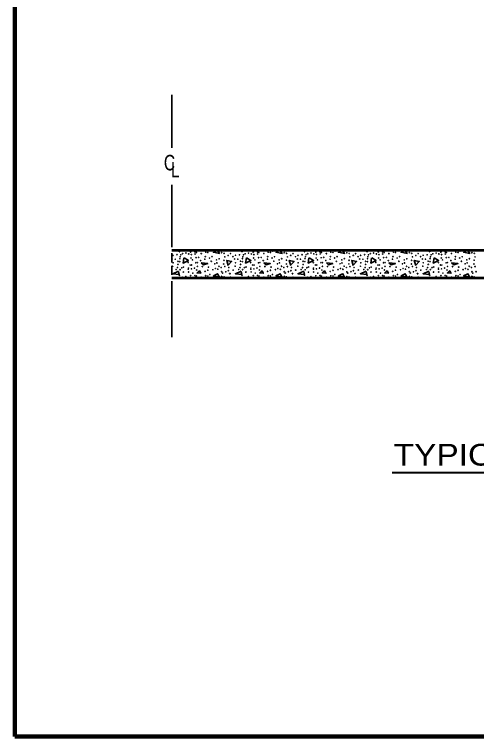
# Model space of a CAD drawing. Extents: x -89 to 766, y -60 to 484.
# Drawn here: x -31.9 to 57.5, y -48 to 91.5 of the extents above; entities that cross this region are included whole.
import ezdxf
from ezdxf.enums import TextEntityAlignment as Align

# ---------------------------------------------------------------- set-up
doc = ezdxf.new("R2010")
doc.units = 0
doc.header["$LTSCALE"] = 1.1
doc.layers.add('1', color=7, linetype='Continuous', lineweight=35)

msp = doc.modelspace()

# ---------------------------------------------------------------- linework, layer by layer
at = {"layer": '1'}
for p, q in [((-1.421, 65.77), (-1.421, 75.97)), ((-1.421, 46.57), (-1.421, 58.57)), ((-1.421, 45.37), (-1.421, 43.57)), ((-1.421, 42.97), (-1.421, 41.17)), ((-1.421, 39.97), (-1.421, 29.17))]:
    msp.add_line(p, q, dxfattribs=at)
at = {"layer": '1', "lineweight": 53}
msp.add_line((112.579, 40.57), (-1.421, 40.57), dxfattribs=at)
at = {"layer": '1', "lineweight": 40}
msp.add_line((41.13, 3.01), (157.278, 3.01), dxfattribs=at)
at = {"layer": '1', "lineweight": 158}
msp.add_line((759.817, -48.017), (-31.783, -48.017), dxfattribs=at)
msp.add_lwpolyline([(759.817, 478.083), (-31.883, 477.983), (-31.783, -48.017)], dxfattribs=at)
at = {"layer": '1', "lineweight": 53}
msp.add_lwpolyline([(-1.421, 45.97), (112.579, 45.97), (112.579, 43.567), (112.579, 40.57)], dxfattribs=at)
at = {"layer": '1'}
for points in [[(-1.143, 45.97), (-0.01, 45.839), (-0.038, 45.97)], [(10.953, 45.97), (12.086, 45.839), (12.058, 45.97)], [(23.049, 45.97), (24.182, 45.839), (24.154, 45.97)], [(35.145, 45.97), (36.278, 45.839), (36.25, 45.97)], [(47.241, 45.97), (48.374, 45.839), (48.346, 45.97)], [(0.926, 44.471), (1.766, 43.991), (0.734, 43.487), (0.878, 44.495)], [(9.446, 43.031), (9.158, 43.991), (10.094, 43.799), (9.422, 43.079)], [(13.022, 44.471), (13.862, 43.991), (12.83, 43.487), (12.974, 44.495)], [(21.542, 43.031), (21.254, 43.991), (22.19, 43.799), (21.518, 43.079)], [(25.118, 44.471), (25.958, 43.991), (24.926, 43.487), (25.07, 44.495)], [(33.638, 43.031), (33.35, 43.991), (34.286, 43.799), (33.614, 43.079)], [(37.214, 44.471), (38.054, 43.991), (37.022, 43.487), (37.166, 44.495)], [(45.734, 43.031), (45.446, 43.991), (46.382, 43.799), (45.71, 43.079)], [(49.31, 44.471), (50.15, 43.991), (49.118, 43.487), (49.262, 44.495)], [(-0.13, 41.879), (-1.258, 41.423), (-0.01, 41.279), (-0.13, 41.831)], [(3.902, 42.047), (3.446, 41.567), (4.142, 41.519), (3.902, 41.999)], [(11.966, 41.879), (10.838, 41.423), (12.086, 41.279), (11.966, 41.831)], [(15.998, 42.047), (15.542, 41.567), (16.238, 41.519), (15.998, 41.999)], [(24.062, 41.879), (22.934, 41.423), (24.182, 41.279), (24.062, 41.831)], [(28.094, 42.047), (27.638, 41.567), (28.334, 41.519), (28.094, 41.999)], [(36.158, 41.879), (35.03, 41.423), (36.278, 41.279), (36.158, 41.831)], [(40.19, 42.047), (39.734, 41.567), (40.43, 41.519), (40.19, 41.999)], [(48.254, 41.879), (47.126, 41.423), (48.374, 41.279), (48.254, 41.831)], [(52.286, 42.047), (51.83, 41.567), (52.526, 41.519), (52.286, 41.999)], [(7.382, 41.423), (6.59, 40.991), (7.766, 40.775), (7.334, 41.447)], [(19.478, 41.423), (18.686, 40.991), (19.862, 40.775), (19.43, 41.447)], [(31.574, 41.423), (30.782, 40.991), (31.958, 40.775), (31.526, 41.447)], [(43.67, 41.423), (42.878, 40.991), (44.054, 40.775), (43.622, 41.447)], [(55.766, 41.423), (54.974, 40.991), (56.15, 40.775), (55.718, 41.447)]]:
    msp.add_lwpolyline(points, dxfattribs=at)
for points in [[(7.358, 45.97), (6.59, 45.551), (7.766, 45.335)], [(19.454, 45.97), (18.686, 45.551), (19.862, 45.335)], [(31.55, 45.97), (30.782, 45.551), (31.958, 45.335)], [(43.646, 45.97), (42.878, 45.551), (44.054, 45.335)], [(55.742, 45.97), (54.974, 45.551), (56.15, 45.335)], [(4.238, 43.535), (5.486, 43.391), (4.67, 43.103)], [(16.334, 43.535), (17.582, 43.391), (16.766, 43.103)], [(28.43, 43.535), (29.678, 43.391), (28.862, 43.103)], [(40.526, 43.535), (41.774, 43.391), (40.958, 43.103)], [(52.622, 43.535), (53.87, 43.391), (53.054, 43.103)]]:
    msp.add_lwpolyline(points, close=True, dxfattribs=at)
for centre in [(-1.232, 44.974), (-0.453, 45.085), (0.024, 45.673), (0.183, 44.687), (0.31, 45.069), (0.644, 45.276), (1.28, 45.419), (1.821, 45.244), (2.203, 45.594), (2.33, 45.117), (3.03, 45.61), (3.046, 45.228), (3.309, 45.514), (4.248, 45.308), (5.011, 44.703), (5.106, 45.578), (5.52, 45.53), (5.902, 45.817), (6.315, 44.703), (8.192, 45.467), (8.653, 45.355), (8.796, 44.671), (9.448, 44.958), (9.893, 45.292), (10.371, 44.703), (10.864, 44.974), (11.643, 45.085), (12.12, 45.673), (12.279, 44.687), (12.406, 45.069), (12.74, 45.276), (13.376, 45.419), (13.917, 45.244), (14.299, 45.594), (14.426, 45.117), (15.126, 45.61), (15.142, 45.228), (15.405, 45.514), (16.344, 45.308), (17.107, 44.703), (17.202, 45.578), (17.616, 45.53), (17.998, 45.817), (18.411, 44.703), (20.288, 45.467), (20.749, 45.355), (20.892, 44.671), (21.544, 44.958), (21.989, 45.292), (22.467, 44.703), (22.96, 44.974), (23.739, 45.085), (24.216, 45.673), (24.375, 44.687), (24.502, 45.069), (24.836, 45.276), (25.472, 45.419), (26.013, 45.244), (26.395, 45.594), (26.522, 45.117), (27.222, 45.61), (27.238, 45.228), (27.501, 45.514), (28.44, 45.308), (29.203, 44.703), (29.298, 45.578), (29.712, 45.53), (30.094, 45.817), (30.507, 44.703), (32.384, 45.467), (32.845, 45.355), (32.988, 44.671), (33.64, 44.958), (34.085, 45.292), (34.563, 44.703), (35.056, 44.974), (35.835, 45.085), (36.312, 45.673), (36.471, 44.687), (36.598, 45.069), (36.932, 45.276), (37.568, 45.419), (38.109, 45.244), (38.491, 45.594), (38.618, 45.117), (39.318, 45.61), (39.334, 45.228), (39.597, 45.514), (40.536, 45.308), (41.299, 44.703), (41.394, 45.578), (41.808, 45.53), (42.19, 45.817), (42.603, 44.703), (44.48, 45.467), (44.941, 45.355), (45.084, 44.671), (45.736, 44.958), (46.181, 45.292), (46.659, 44.703), (47.152, 44.974), (47.931, 45.085), (48.408, 45.673), (48.567, 44.687), (48.694, 45.069), (49.028, 45.276), (49.664, 45.419), (50.205, 45.244), (50.587, 45.594), (50.714, 45.117), (51.414, 45.61), (51.43, 45.228), (51.693, 45.514), (52.632, 45.308), (53.395, 44.703), (53.49, 45.578), (53.904, 45.53), (54.286, 45.817), (54.699, 44.703), (56.576, 45.467), (57.037, 45.355), (57.18, 44.671), (-1.201, 43.526), (-0.771, 44.226), (-0.262, 43.828), (0.088, 43.749), (0.103, 44.321), (1.71, 43.574), (2.266, 44.449), (2.537, 44.098), (3.213, 43.539), (3.237, 44.512), (3.484, 43.558), (3.739, 44.576), (4.136, 43.955), (4.947, 44.226), (5.838, 44.449), (6.172, 43.828), (6.888, 43.335), (7.222, 44.098), (7.269, 43.51), (7.715, 44.305), (8.589, 43.303), (8.637, 44.019), (10.705, 44.258), (10.895, 43.526), (11.325, 44.226), (11.834, 43.828), (12.184, 43.749), (12.199, 44.321), (13.806, 43.574), (14.362, 44.449), (14.633, 44.098), (15.309, 43.539), (15.333, 44.512), (15.58, 43.558), (15.835, 44.576), (16.232, 43.955), (17.043, 44.226), (17.934, 44.449), (18.268, 43.828), (18.984, 43.335), (19.318, 44.098), (19.365, 43.51), (19.811, 44.305), (20.685, 43.303), (20.733, 44.019), (22.801, 44.258), (22.991, 43.526), (23.421, 44.226), (23.93, 43.828), (24.28, 43.749), (24.295, 44.321), (25.902, 43.574), (26.458, 44.449), (26.729, 44.098), (27.405, 43.539), (27.429, 44.512), (27.676, 43.558), (27.931, 44.576), (28.328, 43.955), (29.139, 44.226), (30.03, 44.449), (30.364, 43.828), (31.08, 43.335), (31.414, 44.098), (31.461, 43.51), (31.907, 44.305), (32.781, 43.303), (32.829, 44.019), (34.897, 44.258), (35.087, 43.526), (35.517, 44.226), (36.026, 43.828), (36.376, 43.749), (36.391, 44.321), (37.998, 43.574), (38.554, 44.449), (38.825, 44.098), (39.501, 43.539), (39.525, 44.512), (39.772, 43.558), (40.027, 44.576), (40.424, 43.955), (41.235, 44.226), (42.126, 44.449), (42.46, 43.828), (43.176, 43.335), (43.51, 44.098), (43.557, 43.51), (44.003, 44.305), (44.877, 43.303), (44.925, 44.019), (46.993, 44.258), (47.183, 43.526), (47.613, 44.226), (48.122, 43.828), (48.472, 43.749), (48.487, 44.321), (50.094, 43.574), (50.65, 44.449), (50.921, 44.098), (51.597, 43.539), (51.621, 44.512), (51.868, 43.558), (52.123, 44.576), (52.52, 43.955), (53.331, 44.226), (54.222, 44.449), (54.556, 43.828), (55.272, 43.335), (55.606, 44.098), (55.653, 43.51), (56.099, 44.305), (56.973, 43.303), (57.021, 44.019), (-1.28, 42.874), (-0.612, 42.227), (-0.358, 42.603), (-0.246, 43.208), (0.151, 42.179), (0.485, 42.571), (0.819, 42.714), (1.742, 42.291), (1.758, 42.492), (2.107, 43.096), (2.346, 42.354), (2.378, 43.096), (2.934, 42.508), (3.373, 42.132), (3.484, 42.842), (4.454, 42.794), (4.979, 41.877), (5.52, 42.084), (5.647, 42.699), (6.49, 42.195), (6.967, 42.428), (7.444, 42.275), (7.683, 42.858), (8.112, 42.619), (8.812, 42.794), (9.48, 41.989), (9.591, 42.619), (10.418, 42.116), (10.816, 42.874), (11.484, 42.227), (11.738, 42.603), (11.85, 43.208), (12.247, 42.179), (12.581, 42.571), (12.915, 42.714), (13.838, 42.291), (13.854, 42.492), (14.203, 43.096), (14.442, 42.354), (14.474, 43.096), (15.03, 42.508), (15.469, 42.132), (15.58, 42.842), (16.55, 42.794), (17.075, 41.877), (17.616, 42.084), (17.743, 42.699), (18.586, 42.195), (19.063, 42.428), (19.54, 42.275), (19.779, 42.858), (20.208, 42.619), (20.908, 42.794), (21.576, 41.989), (21.687, 42.619), (22.514, 42.116), (22.912, 42.874), (23.58, 42.227), (23.834, 42.603), (23.946, 43.208), (24.343, 42.179), (24.677, 42.571), (25.011, 42.714), (25.934, 42.291), (25.95, 42.492), (26.299, 43.096), (26.538, 42.354), (26.57, 43.096), (27.126, 42.508), (27.565, 42.132), (27.676, 42.842), (28.646, 42.794), (29.171, 41.877), (29.712, 42.084), (29.839, 42.699), (30.682, 42.195), (31.159, 42.428), (31.636, 42.275), (31.875, 42.858), (32.304, 42.619), (33.004, 42.794), (33.672, 41.989), (33.783, 42.619), (34.61, 42.116), (35.008, 42.874), (35.676, 42.227), (35.93, 42.603), (36.042, 43.208), (36.439, 42.179), (36.773, 42.571), (37.107, 42.714), (38.03, 42.291), (38.046, 42.492), (38.395, 43.096), (38.634, 42.354), (38.666, 43.096), (39.222, 42.508), (39.661, 42.132), (39.772, 42.842), (40.742, 42.794), (41.267, 41.877), (41.808, 42.084), (41.935, 42.699), (42.778, 42.195), (43.255, 42.428), (43.732, 42.275), (43.971, 42.858), (44.4, 42.619), (45.1, 42.794), (45.768, 41.989), (45.879, 42.619), (46.706, 42.116), (47.104, 42.874), (47.772, 42.227), (48.026, 42.603), (48.138, 43.208), (48.535, 42.179), (48.869, 42.571), (49.203, 42.714), (50.126, 42.291), (50.142, 42.492), (50.491, 43.096), (50.73, 42.354), (50.762, 43.096), (51.318, 42.508), (51.757, 42.132), (51.868, 42.842), (52.838, 42.794), (53.363, 41.877), (53.904, 42.084), (54.031, 42.699), (54.874, 42.195), (55.351, 42.428), (55.828, 42.275), (56.067, 42.858), (56.496, 42.619), (57.196, 42.794), (0.024, 41.113), (0.644, 40.716), (0.787, 41.734), (1.28, 40.859), (1.789, 41.75), (1.821, 40.684), (2.203, 41.034), (2.6, 41.527), (3.03, 41.05), (3.046, 40.668), (3.309, 40.954), (4.248, 40.748), (5.106, 41.018), (5.52, 40.97), (5.902, 41.257), (8.192, 41.798), (8.192, 40.907), (8.383, 41.543), (8.653, 40.795), (9.003, 41.798), (9.75, 41.432), (9.814, 41.432), (9.893, 40.732), (12.12, 41.113), (12.74, 40.716), (12.883, 41.734), (13.376, 40.859), (13.885, 41.75), (13.917, 40.684), (14.299, 41.034), (14.696, 41.527), (15.126, 41.05), (15.142, 40.668), (15.405, 40.954), (16.344, 40.748), (17.202, 41.018), (17.616, 40.97), (17.998, 41.257), (20.288, 41.798), (20.288, 40.907), (20.479, 41.543), (20.749, 40.795), (21.099, 41.798), (21.846, 41.432), (21.91, 41.432), (21.989, 40.732), (24.216, 41.113), (24.836, 40.716), (24.979, 41.734), (25.472, 40.859), (25.981, 41.75), (26.013, 40.684), (26.395, 41.034), (26.792, 41.527), (27.222, 41.05), (27.238, 40.668), (27.501, 40.954), (28.44, 40.748), (29.298, 41.018), (29.712, 40.97), (30.094, 41.257), (32.384, 41.798), (32.384, 40.907), (32.575, 41.543), (32.845, 40.795), (33.195, 41.798), (33.942, 41.432), (34.006, 41.432), (34.085, 40.732), (36.312, 41.113), (36.932, 40.716), (37.075, 41.734), (37.568, 40.859), (38.077, 41.75), (38.109, 40.684), (38.491, 41.034), (38.888, 41.527), (39.318, 41.05), (39.334, 40.668), (39.597, 40.954), (40.536, 40.748), (41.394, 41.018), (41.808, 40.97), (42.19, 41.257), (44.48, 41.798), (44.48, 40.907), (44.671, 41.543), (44.941, 40.795), (45.291, 41.798), (46.038, 41.432), (46.102, 41.432), (46.181, 40.732), (48.408, 41.113), (49.028, 40.716), (49.171, 41.734), (49.664, 40.859), (50.173, 41.75), (50.205, 40.684), (50.587, 41.034), (50.984, 41.527), (51.414, 41.05), (51.43, 40.668), (51.693, 40.954), (52.632, 40.748), (53.49, 41.018), (53.904, 40.97), (54.286, 41.257), (56.576, 41.798), (56.576, 40.907), (56.767, 41.543), (57.037, 40.795), (57.387, 41.798)]:
    msp.add_circle(centre, 0.0318, dxfattribs=at)
for centre, start, end in [((9.75, 45.992), 223.38683, 316.61317), ((9.814, 45.992), 223.38683, 316.61317), ((21.846, 45.992), 223.38683, 316.61317), ((21.91, 45.992), 223.38683, 316.61317), ((33.942, 45.992), 223.38683, 316.61317), ((34.006, 45.992), 223.38683, 316.61317), ((46.038, 45.992), 223.38683, 316.61317), ((46.102, 45.992), 223.38683, 316.61317), ((-1.391, 44.258), 201.63508, 158.36492), ((2.33, 40.557), 24.63166, 155.36834), ((14.426, 40.557), 24.63166, 155.36834), ((26.522, 40.557), 24.63166, 155.36834), ((38.618, 40.557), 24.63166, 155.36834), ((50.714, 40.557), 24.63166, 155.36834)]:
    msp.add_arc(centre, 0.0318, start, end, dxfattribs=at)

# ---------------------------------------------------------------- texts
at = {"layer": '1', "width": 0.75}
for s, p in [('C', (-2.984, 61.381)), ('L', (-1.627, 60.023))]:
    msp.add_text(s, height=3, dxfattribs=at).set_placement(p)
at = {"layer": '1', "width": 1.15}
msp.add_text('TYPICAL SECTION WITH GUARDRAIL', height=4.2, dxfattribs=at).set_placement((99.063, 4.341), align=Align.CENTER)

doc.saveas('drawing.dxf')
